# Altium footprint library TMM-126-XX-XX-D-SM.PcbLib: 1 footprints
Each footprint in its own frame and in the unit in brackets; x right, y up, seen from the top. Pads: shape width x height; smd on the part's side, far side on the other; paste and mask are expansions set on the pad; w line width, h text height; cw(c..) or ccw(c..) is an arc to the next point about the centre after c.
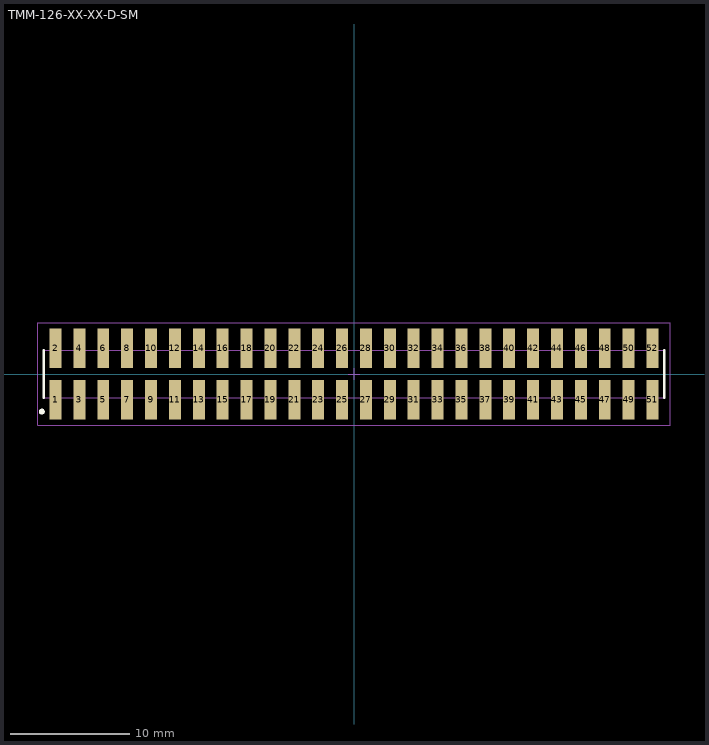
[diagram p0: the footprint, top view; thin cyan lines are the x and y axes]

## TMM-126-XX-XX-D-SM [mm] "2.00mm pitch, 52 pin, terminal strip; double row, SMT"
height 2.77
pads (52):
  rect 1x3.3 smd mask+0: 1(-25,-2.15) 2(-25,2.15) 3(-23,-2.15) 4(-23,2.15) 5(-21,-2.15) 6(-21,2.15) 7(-19,-2.15) 8(-19,2.15) 9(-17,-2.15) 10(-17,2.15) 11(-15,-2.15) 12(-15,2.15) 13(-13,-2.15) 14(-13,2.15) 15(-11,-2.15) 16(-11,2.15) 17(-9,-2.15) 18(-9,2.15) 19(-7,-2.15) 20(-7,2.15) 21(-5,-2.15) 22(-5,2.15) 23(-3,-2.15) 24(-3,2.15) 25(-1,-2.15) 26(-1,2.15) 27(1,-2.15) 28(1,2.15) 29(3,-2.15) 30(3,2.15) 31(5,-2.15) 32(5,2.15) 33(7,-2.15) 34(7,2.15) 35(9,-2.15) 36(9,2.15) 37(11,-2.15) 38(11,2.15) 39(13,-2.15) 40(13,2.15) 41(15,-2.15) 42(15,2.15) 43(17,-2.15) 44(17,2.15) 45(19,-2.15) 46(19,2.15) 47(21,-2.15) 48(21,2.15) 49(23,-2.15) 50(23,2.15) 51(25,-2.15) 52(25,2.15)
Top Overlay:
  circle w0.25: c-26.15,-3.15 r0.125
  lines w0.2: -26,-2 -26,2 ; 26,-2 26,2
Mechanical 12:
  lines w0.001: -26,-2 26,-2 26,2 -26,2 -26,-2
Mechanical 13:
  lines w0.1: -26,-2 26,-2 26,2 -26,2 -26,-2
  text ".Designator" at 0,-0.127 h1.52
Mechanical 15:
  lines w0.05: -0.5,0 0.5,0 ; 0,-0.5 0,0.5 ; -26.5,-4.3 26.5,-4.3 26.5,4.3 -26.5,4.3 -26.5,-4.3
